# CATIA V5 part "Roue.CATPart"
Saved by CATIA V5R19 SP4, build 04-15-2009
Part number: Roue
Bounding box of the stored display mesh (mm): x -246 to 94, y 1643.821 to 1843.821, z -311.409 to -111.804
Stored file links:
  G:\EU_thinkMotion\CFAO_2010\MMS_groupe1\MMS_groupe1\OK\rragonneau\rragonneau\Roue.CATPart
  F:\Squelette\Deambulateur.CATProduct
  G:\EU_thinkMotion\CFAO_2010\MMS_groupe1\MMS_groupe1\OK\rragonneau\rragonneau\Squelette bati.CATPart
  G:\EU_thinkMotion\CFAO_2010\MMS_groupe1\MMS_groupe1\OK\rragonneau\rragonneau\Montants.CATPart
  G:\EU_thinkMotion\CFAO_2010\MMS_groupe1\MMS_groupe1\OK\rragonneau\rragonneau\squelette de base.CATPart
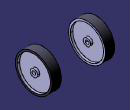
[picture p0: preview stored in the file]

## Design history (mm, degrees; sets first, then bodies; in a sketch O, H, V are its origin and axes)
External parameters (linked from other documents)
  `External.diam_moyeu_ext / epaisseur_bras&montant` = 60 mm
  External.diam_roue = 200 mm
Set1
  Plane1: linked copy from another document
  Plane2: linked copy from another document
  DatumCurve1: linked copy from another document
Body1 (main body)
  Sketch1 on Plane1, origin (94, 0, 0), H (0, 1, 0), V (0, 0, 1)
    circle A1 centre (1743.8211, -211.6064) radius 100
    radius A1 = 100 {= External.diam_roue /2}
  Pad1: profile Sketch1, direction (-1, 0, 0), length 50 {= External.diam_roue /4}
  Sketch2 on start face of Pad1, origin (94, 1743.8211, -211.6064), H (0, 1, 0), V (0, 0, 1)
    point P1 (0, 0)
  Hole1: placed by Sketch2, at (94, 1743.8211, -211.6064) direction (-1, 0, 0), diameter 20, through (limit type 3)
  Sketch3 on start face of Pad1, origin (94, 0, 0), H (0, 1, 0), V (0, 0, 1)
    circle A1 centre (1743.8211, -211.6064) radius 90
    circle A2 centre (1743.8211, -211.6064) radius 20
    reference projected arc E1 centre (1743.8211, -211.6064) radius 20 from (1725.2134, -218.9381) to (1763.8171, -211.2062) ccw from edge of DatumCurve1
    radius A1 = 90 {= External.diam_roue /2-10mm}
    radius A2 = 20
    concentricity: E1 A2, A1 A2
  Pocket1: profile Sketch3, direction (-1, 0, 0), length 12.5 {= External.diam_roue /16}
  Sketch4 on end face of Pad1, origin (44, 0, 0), H (0, 1, 0), V (0, 0, 1)
    circle A1 centre (1743.8211, -211.6064) radius 90
    circle A2 centre (1743.8211, -211.6064) radius 20
    reference projected circle E1 centre (1743.8211, -211.6064) radius 10 from edge [face of Hole1 | end face of Pad1]
    radius A2 = 20
    radius A1 = 90 {= External.diam_roue /2-10mm}
    concentricity: A1 E1, A2 A1
  Pocket2: profile Sketch4, direction (1, 0, 0), length 12.5 {= External.diam_roue /16}
  Mirror1: of Pad1, Hole1, Pocket1, Pocket2, about Plane2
